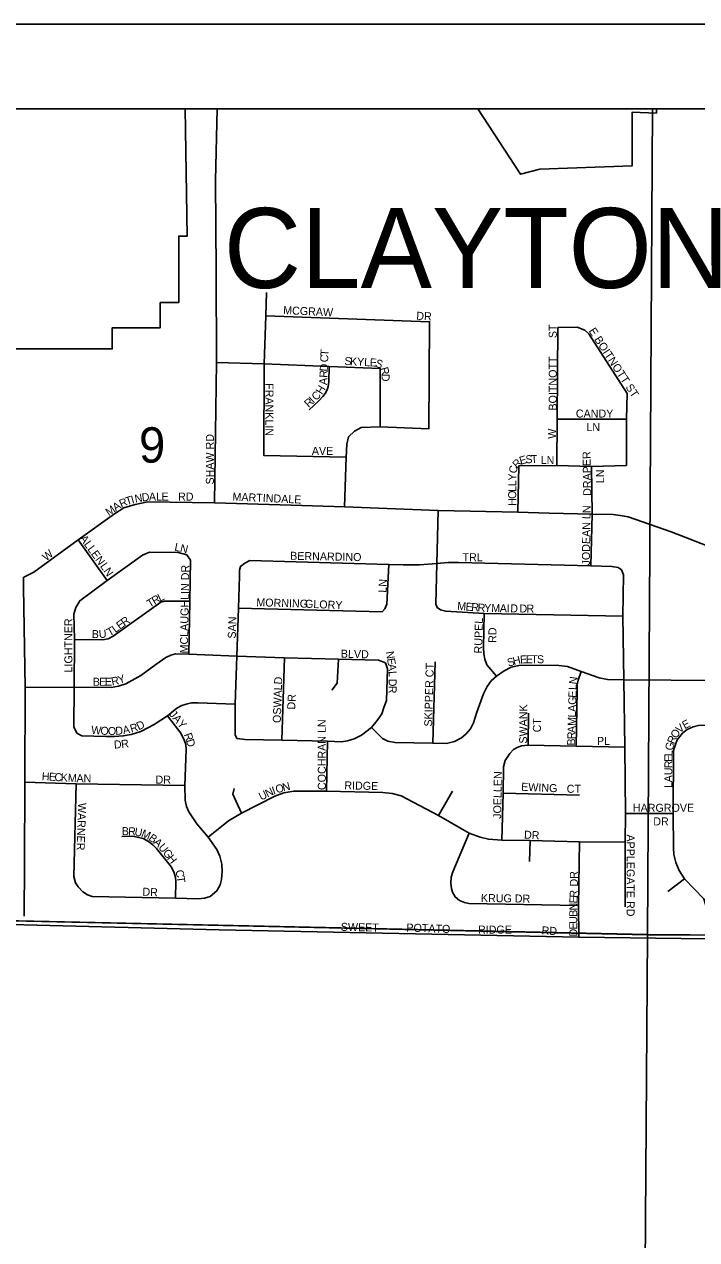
# Model space of a CAD drawing. Extents: x -209 to 4852, y 0 to 905.
# Drawn here: x 332.14 to 348.05, y 311.79 to 340.56 of the extents above; entities that cross this region are included whole.
import ezdxf

# ---------------------------------------------------------------- set-up
doc = ezdxf.new("R2010")
doc.units = 0
for name, color, linetype in [('Default', 7, 'Continuous'), ('GM_X_Airport_Location_Class_2', 7, 'Continuous'), ('GM_X_Airport_Location_Class_3', 7, 'Continuous'), ('GM_X_Corporation_Text', 7, 'Continuous'), ('GM_X_Minor_River', 7, 'Continuous'), ('GM_X_Township_Road_Text', 7, 'Continuous'), ('GM_X_US_Location', 7, 'Continuous'), ('SH_Data', 7, 'Continuous')]:
    doc.layers.add(name, color=color, linetype=linetype)

msp = doc.modelspace()

# ---------------------------------------------------------------- linework, layer by layer
at = {"layer": 'Default'}
msp.add_lwpolyline([(390.832, 338.559), (254.832, 338.559), (254.832, 202.559), (390.832, 202.559)], close=True, dxfattribs=at)
at = {"layer": 'GM_X_Airport_Location_Class_2'}
for points in [[(336.64, 329.238), (336.685, 332.556), (336.677, 334.711), (336.665, 336.864), (336.699, 338.559)], [(339.759, 330.311), (337.804, 330.354), (337.815, 332.524), (337.858, 333.657), (337.871, 334.211)], [(339.719, 329.136), (339.759, 330.311), (339.77, 330.621), (339.815, 330.79), (339.95, 330.926), (340.108, 331.016), (340.56, 331.027), (341.71, 330.982), (341.73, 333.517), (337.858, 333.657)], [(344.747, 330.118), (344.752, 331.213), (344.769, 333.38)], [(346.393, 330.118), (346.392, 331.213), (346.409, 331.816), (345.5, 333.235), (345.407, 333.32), (345.228, 333.388), (344.769, 333.38)], [(336.685, 332.556), (337.815, 332.524), (339.354, 332.46), (340.563, 332.409), (340.56, 331.027)], [(338.88, 331.435), (339.106, 331.647), (339.207, 331.751), (339.258, 331.816), (339.306, 331.906), (339.329, 331.983), (339.346, 332.096), (339.354, 332.46)], [(344.752, 331.213), (346.392, 331.213)], [(343.821, 329.013), (343.843, 330.106), (344.747, 330.118), (345.564, 330.093), (346.393, 330.118)], [(345.579, 328.961), (345.564, 330.093)], [(332.145, 327.482), (332.36, 327.591), (333.411, 328.357), (334.27, 328.973), (334.496, 329.11), (334.76, 329.195), (335.064, 329.254), (336.64, 329.229), (336.64, 329.238)], [(336.64, 329.229), (338.454, 329.174)], [(338.454, 329.174), (339.719, 329.136), (341.937, 329.051), (343.821, 329.013), (344.563, 328.989), (345.579, 328.961), (346.08, 328.958), (346.243, 328.935), (346.433, 328.897), (347.447, 328.544), (347.834, 328.396)], [(341.937, 329.051), (341.902, 327.794), (341.878, 326.829), (341.912, 326.751), (341.991, 326.699), (342.112, 326.664), (343.025, 326.612), (346.306, 326.551)], [(345.546, 327.737), (345.579, 328.961)], [(334.1, 327.396), (333.411, 328.357)], [(347.834, 328.396), (348.669, 328.075), (348.838, 328.019), (349.031, 327.964), (349.244, 327.912), (349.606, 327.893), (351.442, 327.805), (352.012, 327.784), (352.185, 327.778)], [(333.38, 323.78), (333.306, 323.929), (333.32, 324.869), (333.322, 325.995), (333.31, 326.599), (333.355, 326.752), (333.454, 326.913), (334.1, 327.396), (334.935, 327.99), (335.097, 328.062), (335.779, 328.053), (335.985, 327.999)], [(336.035, 325.65), (336.058, 326.901), (336.07, 327.871), (335.985, 327.999)], [(337.172, 323.655), (337.125, 323.737), (337.13, 324.463), (337.166, 325.601), (337.204, 326.738), (337.23, 327.494), (337.235, 327.641), (337.259, 327.727), (337.356, 327.8), (337.478, 327.863), (340.766, 327.773), (341.105, 327.76), (341.496, 327.762), (341.902, 327.794), (342.163, 327.815), (342.417, 327.822), (345.546, 327.737), (346.044, 327.726), (346.197, 327.703)], [(337.204, 326.738), (340.606, 326.652), (340.675, 326.721), (340.719, 326.829), (340.766, 327.773)], [(332.13, 319.443), (332.141, 320.686), (332.149, 322.615), (332.16, 324.863), (332.119, 327.233), (332.115, 327.467), (332.145, 327.482)], [(346.362, 319.671), (346.358, 321.195), (346.368, 321.879), (346.357, 323.448), (346.329, 325.043), (346.306, 326.551), (346.32, 327.526), (346.277, 327.643), (346.197, 327.703)], [(333.322, 325.995), (333.991, 325.989), (334.125, 326.014), (334.239, 326.071), (335.367, 326.882), (335.449, 326.907), (336.058, 326.901)], [(343.312, 325.124), (343.09, 325.396), (343.04, 325.528), (343.014, 325.66), (343.009, 325.807), (343.025, 326.612)], [(332.16, 324.863), (333.32, 324.869), (334.19, 324.861), (334.37, 324.893), (334.54, 324.945), (334.896, 325.144), (335.248, 325.404), (335.484, 325.572), (335.604, 325.623), (335.717, 325.66), (336.035, 325.65), (337.166, 325.601), (338.297, 325.562), (339.576, 325.53), (340.52, 325.503), (340.687, 325.444)], [(337.172, 323.655), (337.368, 323.626), (338.233, 323.609), (339.318, 323.587), (339.643, 323.571), (339.785, 323.598), (339.949, 323.645), (340.118, 323.729), (340.355, 323.912), (340.494, 324.078), (340.598, 324.236), (340.652, 324.384), (340.712, 324.553), (340.734, 325.3), (340.687, 325.444)], [(338.233, 323.609), (338.297, 325.562)], [(339.419, 324.797), (339.542, 324.965), (339.576, 325.53)], [(341.811, 323.539), (341.866, 325.467)], [(340.355, 323.912), (340.616, 323.651), (340.741, 323.587), (340.911, 323.554), (341.811, 323.539), (342.131, 323.532), (342.322, 323.584), (342.487, 323.666), (342.59, 323.755), (342.699, 323.885), (342.768, 324.022), (342.85, 324.275), (343.01, 324.706), (343.091, 324.881), (343.19, 325.02), (343.312, 325.124), (343.496, 325.256), (343.662, 325.338), (343.885, 325.39), (344.792, 325.383), (345, 325.36), (345.32, 325.241), (345.743, 325.085), (345.944, 325.048), (346.329, 325.043)], [(345.198, 323.471), (345.223, 324.79), (345.223, 324.927), (345.245, 325.037), (345.32, 325.241)], [(346.329, 325.043), (348.559, 325.029), (351.222, 325.037), (352.931, 325.025)], [(333.38, 323.78), (333.497, 323.717), (334.068, 323.702), (334.274, 323.697), (334.48, 323.713), (334.664, 323.748), (334.893, 323.821), (335.214, 323.986), (335.53, 324.192), (335.75, 324.371), (335.865, 324.435), (335.966, 324.467), (336.094, 324.495), (336.243, 324.497), (337.13, 324.463)], [(335.934, 322.539), (335.971, 323.394), (335.959, 323.514), (335.926, 323.596), (335.839, 323.778), (335.53, 324.192)], [(344.063, 323.496), (344.074, 324.249)], [(348.297, 318.913), (348.289, 319.579), (348.262, 319.731), (348.226, 319.858), (347.764, 320.33), (347.641, 320.528), (347.564, 320.719), (347.514, 320.909), (347.508, 321.062), (347.494, 321.876), (347.505, 323.367), (347.554, 323.507), (347.596, 323.617), (347.716, 323.776), (347.825, 323.866), (347.97, 323.929), (348.098, 323.963), (348.549, 323.969), (349.258, 323.957), (349.425, 323.929), (349.53, 323.878), (349.675, 323.804)], [(339.29, 322.407), (339.318, 323.587)], [(343.443, 321.242), (343.47, 322.356), (343.482, 322.982), (343.524, 323.131), (343.629, 323.301), (343.721, 323.395), (343.808, 323.44), (343.907, 323.477), (344.063, 323.496), (345.198, 323.471), (346.357, 323.448)], [(332.149, 322.615), (333.365, 322.583), (335.934, 322.539)], [(333.365, 322.583), (333.307, 320.389), (333.35, 320.239), (333.416, 320.14), (333.519, 320.023), (333.63, 319.948), (333.741, 319.913), (335.714, 319.87), (336.249, 319.853), (336.399, 319.869), (336.536, 319.914), (336.694, 320.043), (336.775, 320.189), (336.809, 320.316), (336.822, 320.51), (336.81, 320.678), (336.764, 320.868), (336.697, 321.024), (336.493, 321.319), (336.225, 321.636), (336.031, 321.917), (335.977, 322.042), (335.945, 322.191), (335.934, 322.539)], [(336.493, 321.319), (336.973, 321.705), (337.279, 321.887), (338.066, 322.291), (338.283, 322.367), (338.519, 322.407), (339.29, 322.407), (340.627, 322.373), (340.842, 322.351), (341.057, 322.297), (341.941, 321.827), (342.669, 321.41), (342.929, 321.318), (343.128, 321.266), (343.443, 321.242), (344.112, 321.235), (345.278, 321.204), (346.358, 321.195)], [(337.279, 321.887), (337.074, 322.335), (337.109, 322.469)], [(341.941, 321.827), (342.272, 322.409)], [(343.47, 322.356), (345.281, 322.307)], [(346.368, 321.879), (347.494, 321.876)], [(342.669, 321.41), (342.281, 320.493), (342.245, 320.373), (342.232, 320.221), (342.25, 320.103), (342.272, 320.013), (342.338, 319.904), (342.438, 319.816), (342.559, 319.768), (342.662, 319.75), (345.255, 319.697)], [(335.714, 319.87), (335.725, 320.264), (335.714, 320.358), (335.683, 320.469), (335.62, 320.603), (335.269, 321.051), (335.181, 321.137), (335.081, 321.211), (334.952, 321.282), (334.707, 321.339), (334.447, 321.333)], [(344.096, 320.744), (344.112, 321.235)], [(345.265, 318.953), (345.255, 319.697), (345.278, 321.204)], [(347.375, 320.03), (347.764, 320.33)], [(316.179, 319.381), (316.179, 319.381), (323.862, 319.374), (327.054, 319.345), (332.128, 319.242), (336.751, 319.12), (345.265, 318.953), (348.297, 318.913), (351.368, 318.883), (353.631, 318.876)]]:
    msp.add_lwpolyline(points, dxfattribs=at)
at = {"layer": 'GM_X_Minor_River'}
for points in [[(347.007, 338.559), (326.211, 338.559), (326.186, 319.462), (346.887, 319.016)], [(367.206, 338.559), (347.007, 338.559), (346.887, 319.016), (367.019, 318.854)], [(326.186, 319.462), (346.887, 319.016), (346.745, 298.733), (326.211, 298.849)], [(346.887, 319.016), (367.019, 318.854), (366.855, 298.625), (346.745, 298.733)]]:
    msp.add_lwpolyline(points, close=True, dxfattribs=at)
at = {"layer": 'GM_X_US_Location'}
for points in [[(352.833, 310.021), (351.247, 318.735), (353.713, 318.705), (353.701, 318.797), (356.964, 318.729), (356.95, 322.046), (354.466, 322.071), (354.466, 322.706), (350.479, 322.708), (351.204, 318.981), (346.879, 319.001), (332.187, 319.329), (326.197, 319.5), (323.186, 319.5), (323.185, 323.521), (322.632, 323.521), (322.632, 325.533), (319.745, 325.432), (319.548, 329.185), (319.124, 329.185), (319.123, 338.559), (286.601, 338.559)], [(352.833, 310.021), (351.247, 318.735), (353.713, 318.705), (353.701, 318.797), (356.964, 318.729), (356.95, 322.046), (354.466, 322.071), (354.466, 322.706), (350.479, 322.708), (351.204, 318.981), (346.879, 319.001), (332.187, 319.329), (326.197, 319.5), (323.186, 319.5), (323.185, 323.521), (322.632, 323.521), (322.632, 325.533), (319.745, 325.432), (319.548, 329.185), (319.124, 329.185), (319.123, 338.559), (286.601, 338.559)], [(353.551, 338.559), (347.101, 338.559), (347.101, 338.457), (346.524, 338.478), (346.524, 337.207), (344.338, 337.132), (343.881, 337.01), (342.874, 338.559), (335.946, 338.559), (335.996, 335.546), (335.795, 335.546), (335.795, 333.971), (335.356, 333.971), (335.356, 333.377), (334.22, 333.377), (334.22, 332.874), (331.381, 332.874)], [(353.551, 338.559), (347.101, 338.559), (347.101, 338.457), (346.524, 338.478), (346.524, 337.207), (344.338, 337.132), (343.881, 337.01), (342.874, 338.559), (335.946, 338.559), (335.996, 335.546), (335.795, 335.546), (335.795, 333.971), (335.356, 333.971), (335.356, 333.377), (334.22, 333.377), (334.22, 332.874), (331.381, 332.874)], [(326.197, 319.5), (332.187, 319.329), (346.879, 319.001), (351.204, 318.981)], [(326.197, 319.5), (332.187, 319.329), (346.879, 319.001), (351.204, 318.981)]]:
    msp.add_lwpolyline(points, dxfattribs=at)
for points in [[(324.988, 338.559), (324.989, 329.366), (326.182, 329.373), (326.124, 334.2), (331.381, 334.199), (331.381, 332.874), (334.22, 332.874), (334.22, 333.377), (335.356, 333.377), (335.356, 333.971), (335.795, 333.971), (335.795, 335.546), (335.996, 335.546), (335.946, 338.559)], [(324.988, 338.559), (324.989, 329.366), (326.182, 329.373), (326.124, 334.2), (331.381, 334.199), (331.381, 332.874), (334.22, 332.874), (334.22, 333.377), (335.356, 333.377), (335.356, 333.971), (335.795, 333.971), (335.795, 335.546), (335.996, 335.546), (335.946, 338.559)], [(347.101, 338.559), (342.874, 338.559), (343.881, 337.01), (344.338, 337.132), (346.524, 337.207), (346.524, 338.478), (347.101, 338.457)], [(347.101, 338.559), (342.874, 338.559), (343.881, 337.01), (344.338, 337.132), (346.524, 337.207), (346.524, 338.478), (347.101, 338.457)]]:
    msp.add_lwpolyline(points, close=True, dxfattribs=at)
at = {"layer": 'SH_Data'}
for p, q in [((252.832, 340.559), (392.832, 340.559)), ((254.832, 338.559), (390.832, 338.559))]:
    msp.add_line(p, q, dxfattribs=at)

# ---------------------------------------------------------------- texts
at = {"layer": 'GM_X_Airport_Location_Class_3'}
for s, height, rotation, p in [('MCGRAW', 0.1894, 357.3177, (338.262, 333.7)), ('DR', 0.1894, 356.989, (341.413, 333.567)), ('ST', 0.1894, 90, (344.742, 333.131)), ('E BOITNOTT ST', 0.18939, 303.2157, (345.49, 333.301)), ('C', 0.189, 87.4493, (339.329, 332.555)), ('T', 0.189, 87.466, (339.335, 332.705)), ('S', 0.189, 356.8756, (339.712, 332.497)), ('K', 0.189, 356.8756, (339.845, 332.489)), ('Y', 0.189, 356.8756, (340.012, 332.48)), ('L', 0.189, 356.8756, (340.178, 332.471)), ('E', 0.189, 356.8756, (340.311, 332.464)), ('S', 0.189, 342.3964, (340.432, 332.459)), ('BOITNOTT', 0.1894, 90, (344.742, 331.415)), ('R', 0.189, 87.2719, (339.312, 332.189)), ('D', 0.189, 87.4483, (339.319, 332.339)), ('R', 0.189, 284.4793, (340.56, 332.418)), ('FRANKLIN', 0.1894, 270, (337.846, 332.065)), ('A', 0.189, 86.2098, (339.301, 332.018)), ('D', 0.189, 270, (340.596, 332.285)), ('I', 0.189, 42.7736, (338.98, 331.576)), ('C', 0.189, 44.5013, (339.046, 331.637)), ('H', 0.189, 58.6856, (339.184, 331.782)), ('R', 0.189, 42.8014, (338.87, 331.474)), ('CANDY', 0.1894, 0, (345.194, 331.25)), ('W', 0.189, 90, (344.725, 330.748)), ('LN', 0.1894, 0, (345.444, 330.928)), ('SHAW RD', 0.1894, 90, (336.625, 329.665)), ('AVE', 0.1894, 0, (338.944, 330.367)), ('E', 0.189, 16.7733, (343.888, 330.13)), ('S', 0.189, 2.128, (344.003, 330.166)), ('T', 0.189, 2.128, (344.136, 330.171)), ('LN', 0.1894, 0, (344.361, 330.15)), ('DRAPER', 0.1894, 91.0411, (345.559, 329.397)), ('C', 0.189, 75.3547, (343.78, 329.912)), ('R', 0.189, 46.064, (343.805, 330.035)), ('Y', 0.189, 90, (343.781, 329.758)), ('L', 0.189, 90, (343.781, 329.625)), ('LN', 0.1894, 90, (345.864, 329.698)), ('N', 0.189, 10.2853, (334.767, 329.232)), ('D', 0.189, 6.9244, (334.928, 329.261)), ('A', 0.189, 0.8962, (335.088, 329.281)), ('L', 0.189, 0, (335.254, 329.284)), ('E', 0.189, 0, (335.387, 329.284)), ('RD', 0.1894, 0, (335.777, 329.284)), ('MARTINDALE', 0.1894, 357.5094, (337.062, 329.284)), ('O', 0.189, 90, (343.781, 329.325)), ('L', 0.189, 90, (343.781, 329.491)), ('M', 0.189, 34.7712, (334.139, 328.91)), ('A', 0.189, 34.3509, (334.303, 329.024)), ('R', 0.189, 23.5015, (334.433, 329.113)), ('T', 0.189, 17.7697, (334.566, 329.171)), ('I', 0.189, 14.9906, (334.69, 329.211)), ('H', 0.189, 90, (343.781, 329.158)), ('JODEAN LN', 0.1894, 89.2466, (345.525, 327.748)), ('ALLEN', 0.1894, 306.1207, (333.439, 328.385)), ('L', 0.189, 349.0061, (335.682, 328.1)), ('W', 0.189, 38.6625, (332.655, 327.842)), ('N', 0.189, 346.3878, (335.811, 328.075)), ('BERNARDINO', 0.1894, 358.8662, (338.428, 327.884)), ('TRL', 0.1894, 0, (342.511, 327.85)), ('LN', 0.1894, 304.508, (333.923, 327.734)), ('MCLAUGHLIN DR', 0.18939, 89.0128, (336.008, 325.665)), ('LN', 0.1894, 86.9775, (340.708, 327.1)), ('T', 0.189, 31.0669, (335.107, 326.744)), ('R', 0.189, 31.0554, (335.222, 326.813)), ('L', 0.189, 25.3306, (335.346, 326.888)), ('MORNING', 0.1894, 358.2653, (337.628, 326.784)), ('GLORY', 0.1894, 357.6154, (338.779, 326.75)), ('M', 0.189, 355.7522, (342.38, 326.698)), ('E', 0.189, 355.7333, (342.579, 326.683)), ('R', 0.189, 355.7476, (342.712, 326.673)), ('R', 0.189, 355.7466, (342.862, 326.662)), ('Y', 0.189, 358.4052, (343.021, 326.65)), ('M', 0.189, 359.1539, (343.191, 326.646)), ('A', 0.189, 359.182, (343.391, 326.643)), ('I', 0.189, 359.1697, (343.557, 326.64)), ('D', 0.189, 359.182, (343.641, 326.639)), ('D', 0.189, 359.1694, (343.857, 326.636)), ('R', 0.189, 359.1864, (344.024, 326.634)), ('LIGHTNER', 0.1894, 90, (333.275, 325.215)), ('T', 0.189, 29.4889, (334.156, 326.066)), ('L', 0.189, 36.0298, (334.292, 326.145)), ('E', 0.189, 36.2515, (334.4, 326.223)), ('R', 0.189, 36.2578, (334.508, 326.302)), ('SAN', 0.1894, 87.9557, (337.142, 326.016)), ('RUPEL', 0.1894, 88.7317, (342.975, 325.664)), ('RD', 0.1894, 90, (343.314, 325.915)), ('B', 0.189, 357.1327, (333.73, 326.034)), ('U', 0.189, 4.9017, (333.908, 326.027)), ('BLVD', 0.1894, 358.4933, (339.628, 325.567)), ('N', 0.189, 279.3294, (340.695, 325.704)), ('E', 0.189, 279.3306, (340.722, 325.539)), ('A', 0.189, 276.1085, (340.743, 325.411)), ('SKIPPER CT', 0.1894, 88.5129, (341.792, 323.932)), ('S', 0.189, 16.9923, (343.6, 325.349)), ('H', 0.189, 14.1317, (343.725, 325.387)), ('E', 0.189, 3.0889, (343.877, 325.426)), ('E', 0.189, 0.1639, (344.007, 325.433)), ('T', 0.189, 0, (344.141, 325.434)), ('S', 0.189, 0, (344.274, 325.434)), ('R', 0.189, 10.9801, (334.215, 324.907)), ('Y', 0.189, 18.5266, (334.388, 324.943)), ('L', 0.189, 270.6011, (340.761, 325.25)), ('B', 0.189, 0.3643, (333.761, 324.9)), ('E', 0.189, 0.3552, (333.911, 324.901)), ('E', 0.189, 0.6807, (334.045, 324.902)), ('OSWALD', 0.1894, 88.0595, (338.208, 324.016)), ('D', 0.189, 269.9928, (340.762, 325.067)), ('R', 0.189, 269.994, (340.762, 324.9)), ('L', 0.189, 88.4149, (345.211, 324.798)), ('N', 0.189, 82.4819, (345.214, 324.926)), ('DR', 0.1894, 86.9884, (338.547, 324.333)), ('G', 0.189, 88.4258, (345.201, 324.448)), ('E', 0.189, 88.4363, (345.206, 324.615)), ('JAY', 0.1894, 310.1098, (335.555, 324.221)), ('SWANK', 0.1894, 90, (344.042, 323.531)), ('L', 0.189, 88.4363, (345.193, 324.148)), ('A', 0.189, 88.439, (345.197, 324.282)), ('R', 0.189, 16.6799, (334.671, 323.789)), ('D', 0.189, 25.754, (334.845, 323.844)), ('COCHRAN LN', 0.1894, 90, (339.275, 322.431)), ('CT', 0.1894, 90, (344.367, 323.798)), ('M', 0.189, 88.4336, (345.188, 323.948)), ('V', 0.189, 41.3504, (347.658, 323.765)), ('E', 0.189, 28.3248, (347.773, 323.869)), ('W', 0.189, 354.8314, (333.714, 323.767)), ('O', 0.189, 355.984, (333.934, 323.747)), ('O', 0.189, 0.297, (334.116, 323.735)), ('D', 0.189, 4.9384, (334.299, 323.736)), ('A', 0.189, 10.498, (334.485, 323.753)), ('R', 0.189, 290.3855, (335.91, 323.745)), ('R', 0.189, 88.421, (345.179, 323.632)), ('A', 0.189, 88.4502, (345.183, 323.782)), ('PL', 0.1894, 0, (345.694, 323.5)), ('R', 0.189, 67.707, (347.521, 323.507)), ('O', 0.189, 55.9643, (347.573, 323.637)), ('D', 0.189, 4.3099, (334.265, 323.412)), ('R', 0.189, 6.9362, (334.44, 323.425)), ('D', 0.189, 286.873, (335.962, 323.607)), ('B', 0.189, 88.4453, (345.175, 323.482)), ('G', 0.189, 75.4177, (347.481, 323.352)), ('R', 0.189, 89.5072, (347.479, 322.948)), ('E', 0.189, 89.5061, (347.48, 323.098)), ('L', 0.189, 89.5061, (347.481, 323.231)), ('H', 0.189, 356.5232, (332.546, 322.667)), ('E', 0.189, 356.5004, (332.713, 322.657)), ('C', 0.189, 356.5343, (332.846, 322.649)), ('K', 0.189, 356.5249, (332.995, 322.64)), ('M', 0.189, 356.9459, (333.163, 322.629)), ('JOELLEN', 0.1894, 89.0295, (343.425, 321.749)), ('U', 0.189, 89.4972, (347.477, 322.781)), ('A', 0.189, 359.4861, (333.372, 322.618)), ('N', 0.189, 359.9929, (333.541, 322.617)), ('DR', 0.1894, 0, (335.244, 322.584)), ('O', 0.189, 17.1493, (338.115, 322.351)), ('N', 0.189, 14.4232, (338.272, 322.399)), ('RIDGE', 0.1894, 358.6369, (339.711, 322.45)), ('EWING', 0.1894, 357.5069, (343.896, 322.417)), ('CT', 0.1894, 0, (344.977, 322.367)), ('L', 0.189, 89.5082, (347.475, 322.481)), ('A', 0.189, 89.5086, (347.476, 322.614)), ('U', 0.189, 26.0177, (337.744, 322.18)), ('N', 0.189, 25.9981, (337.894, 322.253)), ('I', 0.189, 19.2508, (338.038, 322.324)), ('WARNER', 0.1894, 268.0883, (333.413, 322.13)), ('HARGROVE', 0.1894, 0, (346.544, 321.917)), ('DR', 0.1894, 0, (347.027, 321.595)), ('B', 0.189, 359.0286, (334.443, 321.367)), ('R', 0.189, 357.3765, (334.592, 321.365)), ('U', 0.189, 349.6033, (334.735, 321.358)), ('M', 0.189, 337.8874, (334.889, 321.331)), ('B', 0.189, 323.203, (335.063, 321.262)), ('DR', 0.1894, 356.989, (343.963, 321.284)), ('APPLEGATE RD', 0.18939, 270, (346.396, 321.381)), ('A', 0.189, 318.2939, (335.18, 321.175)), ('U', 0.189, 309.6908, (335.299, 321.07)), ('G', 0.189, 308.0283, (335.405, 320.943)), ('H', 0.189, 307.9977, (335.507, 320.811)), ('C', 0.189, 282.1626, (335.712, 320.523)), ('T', 0.189, 277.3961, (335.743, 320.38)), ('DR', 0.1894, 90, (345.242, 320.148)), ('DR', 0.1894, 356.989, (334.929, 319.933)), ('KRUG DR', 0.1894, 359.0765, (342.945, 319.784)), ('R', 0.189, 87.4978, (345.233, 319.879)), ('N', 0.189, 89.1912, (345.225, 319.581)), ('E', 0.189, 87.7312, (345.228, 319.746)), ('B', 0.189, 89.9687, (345.225, 319.431)), ('U', 0.189, 89.9688, (345.225, 319.265)), ('SWEET', 0.1894, 358.7553, (339.628, 319.1)), ('POTATO', 0.1894, 357.9186, (341.179, 319.084)), ('RIDGE', 0.1894, 0, (342.877, 319.034)), ('RD', 0.1894, 356.989, (344.379, 319.017)), ('E', 0.189, 89.9727, (345.225, 319.131)), ('D', 0.189, 89.9781, (345.225, 318.965))]:
    msp.add_text(s, height=height, rotation=rotation, dxfattribs=at).set_placement(p)
at = {"layer": 'GM_X_Corporation_Text'}
msp.add_text('CLAYTON', height=1.8939, rotation=0, dxfattribs=at).set_placement((336.86, 334.317))
at = {"layer": 'GM_X_Township_Road_Text'}
msp.add_text('9', height=0.837, rotation=0, dxfattribs=at).set_placement((334.852, 330.183))

doc.saveas('drawing.dxf')
